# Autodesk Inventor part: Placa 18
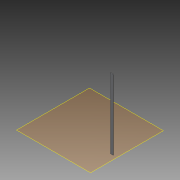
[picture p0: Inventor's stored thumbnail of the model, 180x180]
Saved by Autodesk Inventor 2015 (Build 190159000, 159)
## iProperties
Created: 2015-04
Part Number: Placa 18
Material: Generic
Document SubType Name: Modeling
Designer: suporte
Density: 1 g/cm^3
Appearance: Default
Author: suporte
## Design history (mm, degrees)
workplane "Work Plane1"
sketch "Sketch1"
  geometry: L1 (812.5, 518.558)-(812.5, -400) reference; L2 (852.966, -270)-(872.034, -270) reference; L3 (825, -270)-(900, -270); L4 (900, -270)-(900, -257.5); L5 (900, -257.5)-(825, -257.5); L6 (825, -257.5)-(825, -270); 3 further points
  constraints: 8 end point, 2 midpoint, 2 parallel, 1 coincident, 1 horizontal, 1 perpendicular, 1 point on line
  dimensions: "d2" = 75 distance of L4.end L5.end; "d3" = 12.5 distance of L3.end L4.end
  node "Reference1"
  node "Reference2"
workplane "Work Plane2"
extrude "Extrusion1" new body sketch "Sketch1" stored distance "d4" = 10; taper "d5" = 0 deg
body "Solid1"
